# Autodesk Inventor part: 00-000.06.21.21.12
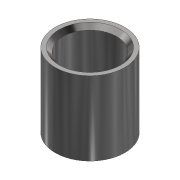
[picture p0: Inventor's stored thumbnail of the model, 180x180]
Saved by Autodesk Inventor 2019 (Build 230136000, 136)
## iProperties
Created: 2019-01
Part Number: 00-000.06.21.21.12
Material: Steel, Mild
Document SubType Name: Modeling
Designer: m.vorobev
Density: 7.85 g/cm^3
Appearance: Semi-Polished
Author: m.vorobev
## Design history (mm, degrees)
derived "00-000.06.21.21.11,12,13.ipt"
feature "Solid1::00-000.06.21.21.11,12,13.ipt"
tag "TaggingFeature1"
body "Solid1"
other parameters: "D1" = 26, "B" = 27.6, "d4" = 1.5
